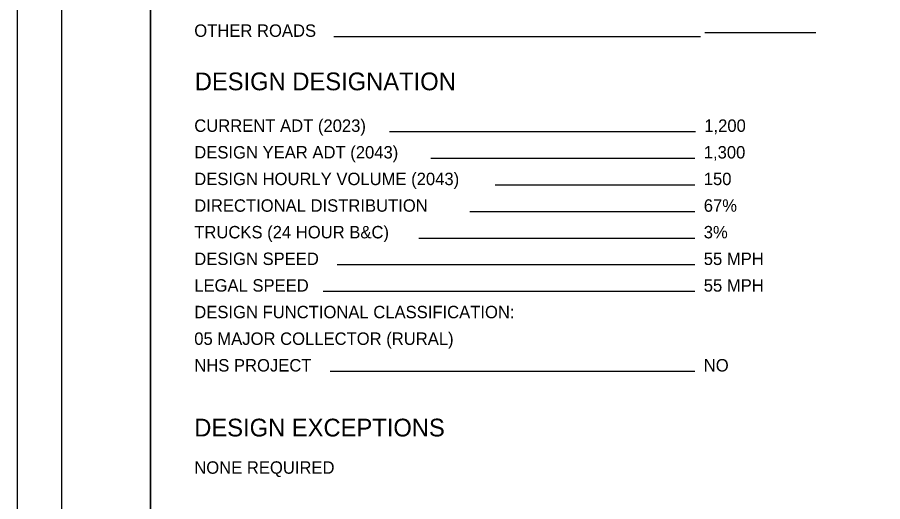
# Model space of a CAD drawing. Extents: x 0 to 34, y 0 to 22.
# Drawn here: x 0 to 9.75, y 5.64 to 11.1 of the extents above; entities that cross this region are included whole.
import ezdxf

# ---------------------------------------------------------------- set-up
doc = ezdxf.new("R2010")
doc.units = 0
for name, color, linetype in [('SH_Border', 7, 'Continuous'), ('SH_Cut_Line', 7, 'Continuous'), ('SH_Data', 7, 'Continuous'), ('SH_Text', 7, 'Continuous')]:
    doc.layers.add(name, color=color, linetype=linetype)

msp = doc.modelspace()

# ---------------------------------------------------------------- linework, layer by layer
at = {"layer": 'SH_Border'}
for points in [[(0.5, 21.5), (1.5, 21.5), (1.5, 0.5), (0.5, 0.5)], [(1.5, 21.5), (33.5, 21.5), (33.5, 0.5), (1.5, 0.5)]]:
    msp.add_lwpolyline(points, close=True, dxfattribs=at)
at = {"layer": 'SH_Cut_Line'}
msp.add_lwpolyline([(0, 0), (34, 0), (34, 22), (0, 22)], close=True, dxfattribs=at)
at = {"layer": 'SH_Data'}
for p, q in [((7.7, 10.8767), (3.5657, 10.8767)), ((9, 10.9223), (7.75, 10.9223)), ((7.6424, 9.8062), (4.1936, 9.8062)), ((7.6368, 9.5062), (4.6592, 9.5062)), ((7.6368, 9.2062), (5.3852, 9.2062)), ((7.6368, 8.9062), (5.0988, 8.9062)), ((7.6368, 8.6062), (4.5259, 8.6062)), ((7.6368, 8.3062), (3.6035, 8.3062)), ((7.6368, 8.0062), (3.4488, 8.0062)), ((7.6368, 7.1062), (3.5243, 7.1062))]:
    msp.add_line(p, q, dxfattribs=at)

# ---------------------------------------------------------------- texts
msp.add_text('DESIGN DESIGNATION', height=0.2, dxfattribs=at).set_placement((2, 10.2747))
at = {"layer": 'SH_Text'}
for s, height, p in [('OTHER ROADS', 0.14, (1.9944, 10.8767)), ('CURRENT ADT (2023)', 0.14, (1.9944, 9.8062)), ('1,200', 0.14, (7.7424, 9.8062)), ('DESIGN YEAR ADT (2043)', 0.14, (1.9944, 9.5062)), ('1,300', 0.14, (7.7368, 9.5062)), ('DESIGN HOURLY VOLUME (2043)', 0.14, (1.9944, 9.2062)), ('150', 0.14, (7.7368, 9.2062)), ('DIRECTIONAL DISTRIBUTION', 0.14, (1.9944, 8.9062)), ('67%', 0.14, (7.7368, 8.9062)), ('TRUCKS (24 HOUR B&C)', 0.14, (1.9944, 8.6062)), ('3%', 0.14, (7.7368, 8.6062)), ('DESIGN SPEED', 0.14, (1.9944, 8.3062)), ('55 MPH', 0.14, (7.7368, 8.3062)), ('LEGAL SPEED', 0.14, (1.9944, 8.0062)), ('55 MPH', 0.14, (7.7368, 8.0062)), ('DESIGN FUNCTIONAL CLASSIFICATION:', 0.14, (1.9944, 7.7062)), ('05 MAJOR COLLECTOR (RURAL)', 0.14, (1.9944, 7.4062)), ('NHS PROJECT', 0.14, (1.9944, 7.1062)), ('NO', 0.14, (7.7368, 7.1062)), ('DESIGN EXCEPTIONS', 0.2, (1.9944, 6.3744)), ('NONE REQUIRED', 0.14, (1.9944, 5.9544))]:
    msp.add_text(s, height=height, dxfattribs=at).set_placement(p)

doc.saveas('drawing.dxf')
